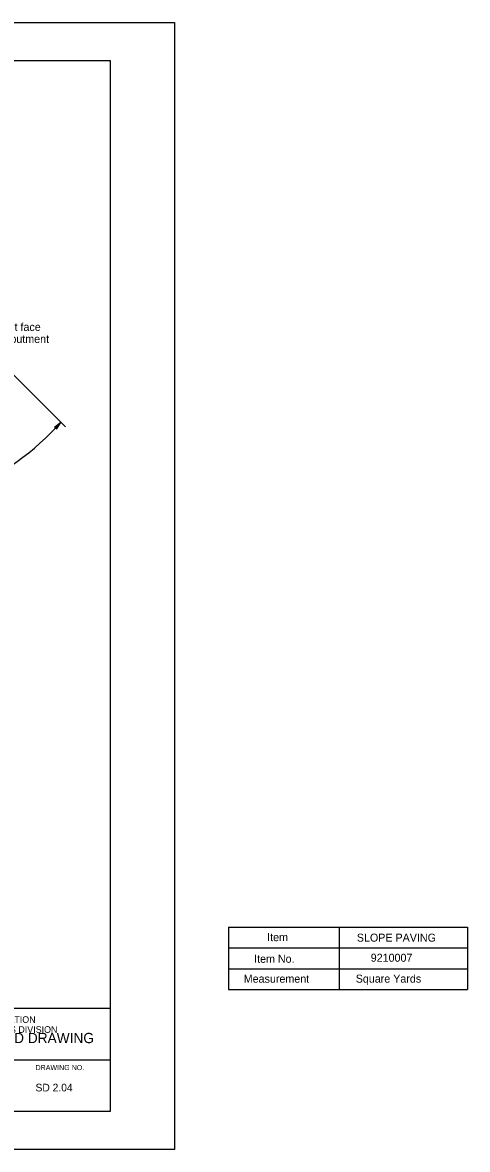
# Model space of a CAD drawing. Extents: x 0 to 3.31, y -0.03 to 1.83.
# Drawn here: x 2.586 to 3.31, y 0 to 1.833 of the extents above; entities that cross this region are included whole.
import ezdxf

# ---------------------------------------------------------------- set-up
doc = ezdxf.new("R2010")
doc.units = 0
for name, color, linetype in [('54', 7, 'Continuous'), ('55', 7, 'Continuous'), ('57', 7, 'Continuous'), ('62', 7, 'Continuous'), ('63', 7, 'Continuous')]:
    doc.layers.add(name, color=color, linetype=linetype)

msp = doc.modelspace()

# ---------------------------------------------------------------- linework, layer by layer
at = {"layer": '54'}
msp.add_lwpolyline([(2.6486, 1.1828), (2.6381, 1.1747), (2.6409, 1.1742), (2.6417, 1.1716)], close=True, dxfattribs=at)
at = {"layer": '55'}
msp.add_line((2.5648, 1.2665), (2.6559, 1.1754), dxfattribs=at)
msp.add_arc((2.3122, 1.4868), 0.4534, 269.7277, 317.8866, dxfattribs=at)
at = {"layer": '57'}
for p, q in [((2.9214, 0.3618), (3.3101, 0.3618)), ((2.9214, 0.3618), (2.9214, 0.2603)), ((3.1016, 0.3618), (3.1016, 0.2603)), ((3.3101, 0.3618), (3.3101, 0.2603)), ((2.9214, 0.328), (3.3101, 0.328)), ((2.9214, 0.2941), (3.3101, 0.2941)), ((2.9214, 0.2603), (3.3101, 0.2603))]:
    msp.add_line(p, q, dxfattribs=at)
at = {"layer": '62'}
for p, q in [((2.7292, 0.2291), (1.8542, 0.2291)), ((2.7292, 0.2291), (1.8542, 0.2291)), ((2.7292, 0.2291), (1.8542, 0.2291)), ((2.1875, 0.1458), (2.7292, 0.1458))]:
    msp.add_line(p, q, dxfattribs=at)
msp.add_lwpolyline([(2.7292, 1.7708), (0.1042, 1.7708), (0.1042, 0.0624), (2.7292, 0.0624)], close=True, dxfattribs=at)
at = {"layer": '63'}
for p, q in [((0, 1.8333), (2.8333, 1.8333)), ((0, 1.8333), (2.8333, 1.8333)), ((0, 1.8333), (2.8333, 1.8333)), ((2.8333, 1.8333), (2.8333, 0)), ((2.8333, 1.8333), (2.8333, 0)), ((2.8333, 1.8333), (2.8333, 0)), ((2.1875, 0.1458), (2.7292, 0.1458)), ((2.1875, 0.1458), (2.7292, 0.1458)), ((2.8333, 0), (0, 0)), ((2.8333, 0), (0, 0)), ((2.8333, 0), (0, 0))]:
    msp.add_line(p, q, dxfattribs=at)
msp.add_lwpolyline([(2.7292, 1.7708), (0.1042, 1.7708), (0.1042, 0.0624), (2.7292, 0.0624)], close=True, dxfattribs=at)

# ---------------------------------------------------------------- texts
at = {"layer": '57'}
for s, height, p in [('Front face', 0.01302, (2.5374, 1.3316)), ('of abutment', 0.013017, (2.5374, 1.3121)), ('Item', 0.01302, (2.9842, 0.3389)), ('SLOPE PAVING', 0.013021, (3.1301, 0.3381)), ('Item No.', 0.01302, (2.963, 0.3037)), ('9210007', 0.01302, (3.1527, 0.3054)), ('Measurement', 0.013021, (2.9461, 0.2713)), ('Square Yards', 0.013021, (3.1283, 0.2714))]:
    msp.add_text(s, height=height, dxfattribs=at).set_placement(p)
at = {"layer": '62'}
for s, height, p in [('ARIZONA DEPARTMENT OF TRANSPORTATION', 0.010833, (2.2775, 0.2059)), ('INFRASTRUCTURE DELIVERY AND OPERATIONS DIVISION', 0.010833, (2.2333, 0.1897)), ('BRIDGE GROUP STANDARD DRAWING', 0.016667, (2.2864, 0.173)), ('DRAWING NO.', 0.008333, (2.6073, 0.1291)), ('SD 2.04', 0.0125, (2.6073, 0.0944))]:
    msp.add_text(s, height=height, dxfattribs=at).set_placement(p)

doc.saveas('drawing.dxf')
